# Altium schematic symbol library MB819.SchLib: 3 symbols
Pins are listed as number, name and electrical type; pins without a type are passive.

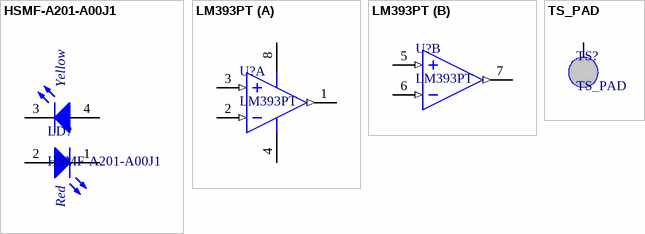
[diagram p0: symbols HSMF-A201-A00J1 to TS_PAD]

## HSMF-A201-A00J1
designator LD?
pins: 1 RED_cathode, 2 Red_anode, 3 YellowGreen_cathode, 4 YellowGreen_anode

## LM393PT
designator U?
footprint TSSOP8 (Footprint not found)
part A pins: 1 OUT (out), 2 IN- (in), 3 IN+ (in), 4 V- (power), 8 V+ (power)
part B pins: 5 IN+ (in), 6 IN- (in), 7 OUT (out)

## TS_PAD
designator TS?
pins: 0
